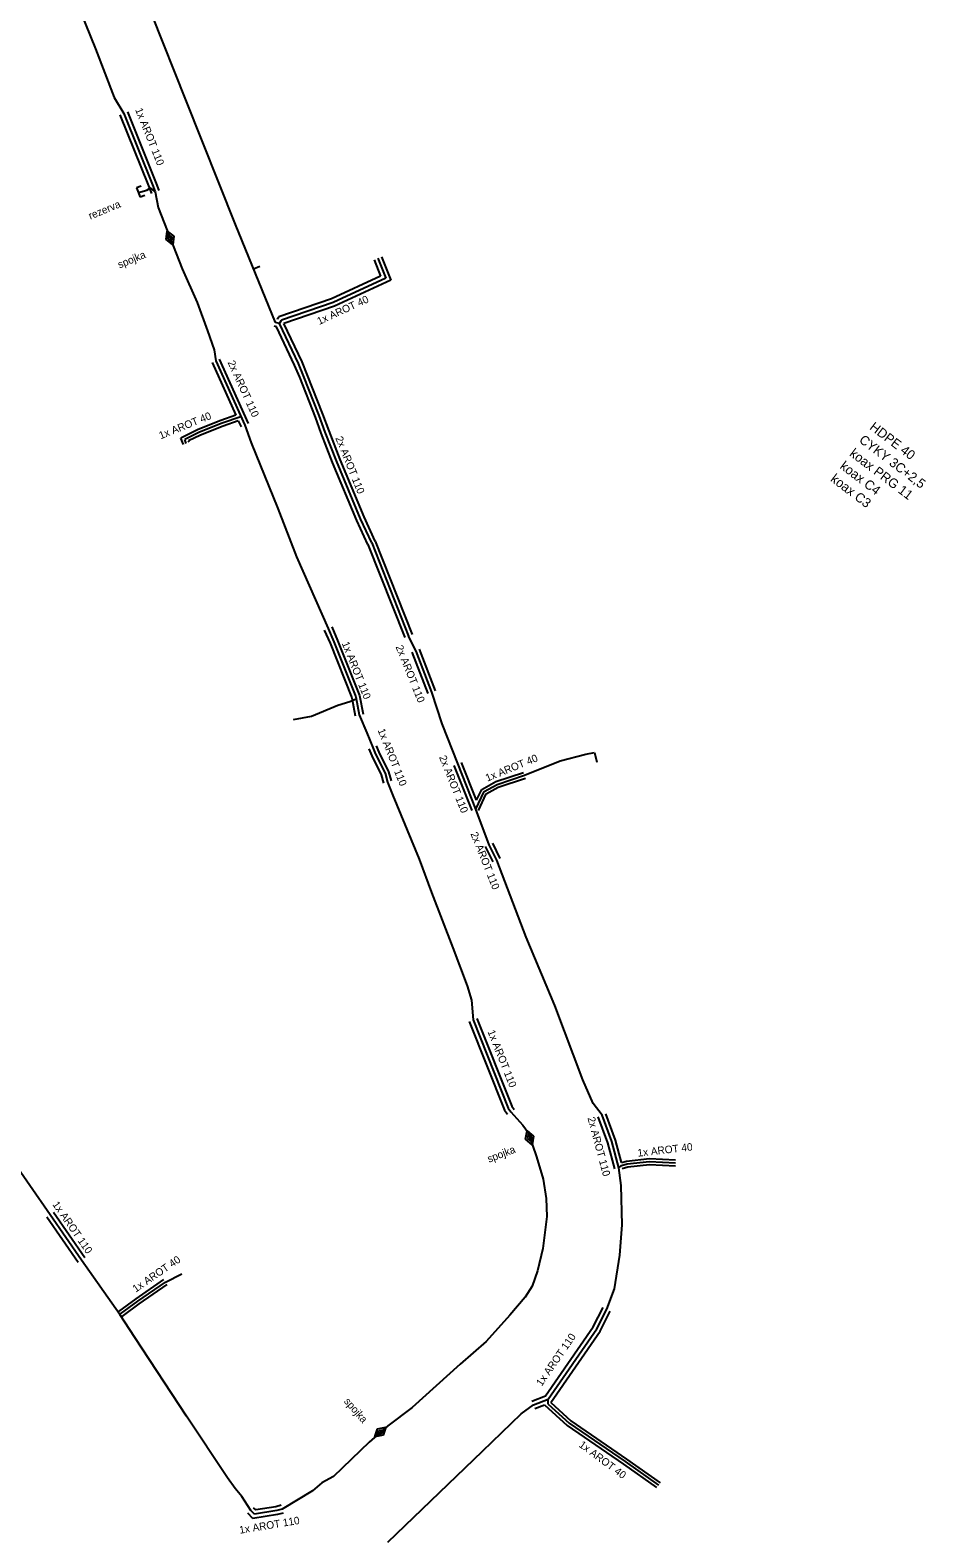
# Model space of a CAD drawing. Extents: x -651943 to -618711, y -1138561 to -1100552.
# Drawn here: x -651407.5 to -651318.3, y -1113276.7 to -1113126.5 of the extents above; entities that cross this region are included whole.
import ezdxf

# ---------------------------------------------------------------- set-up
doc = ezdxf.new("R2010")
doc.units = 0
doc.layers.add('KT trasa', color=7, linetype='Continuous')
doc.layers.add('KT zařízení', color=7, linetype='Continuous')

# ---------------------------------------------------------------- blocks, each defined once
blk = doc.blocks.new('TVSPO_1')
at = {"layer": 'KT zařízení'}
for p, q in [((-0.074, 0.002), (0, 0.044)), ((-0.001, -0.041), (-0.074, 0.002)), ((-0.035, 0), (0, 0.02)), ((0.073, 0.001), (-0.001, -0.041)), ((0, 0.044), (0.073, 0.001)), ((0, 0.02), (0.035, 0)), ((0.035, 0), (0, -0.02)), ((0, -0.02), (-0.035, 0))]:
    blk.add_line(p, q, dxfattribs=at)
blk = doc.blocks.new('TVREZ')
at = {"layer": 'KT zařízení'}
for p, q in [((-0.05, 0.05), (0, 0.05)), ((0, -0.05), (0, 0.05)), ((-0.05, -0.05), (0, -0.05))]:
    blk.add_line(p, q, dxfattribs=at)

msp = doc.modelspace()

# ---------------------------------------------------------------- linework, layer by layer
at = {"layer": 'KT trasa'}
for p, q in [((-651403.1, -1113123.29), (-651401.02, -1113128.38)), ((-651392.02, -1113133.49), (-651395.37, -1113125.03)), ((-651401.02, -1113128.38), (-651399.16, -1113133.25)), ((-651399.16, -1113133.25), (-651398.21, -1113134.82)), ((-651387.09, -1113145.9), (-651392.02, -1113133.49)), ((-651398.21, -1113134.82), (-651395.36, -1113141.93)), ((-651396.74, -1113142.71), (-651395.93, -1113142.46)), ((-651395.93, -1113142.46), (-651395.55, -1113142.24)), ((-651395.08, -1113142.64), (-651395.55, -1113142.24)), ((-651395.36, -1113141.93), (-651395.08, -1113142.64)), ((-651395.08, -1113142.64), (-651394.8, -1113144.21)), ((-651394.8, -1113144.21), (-651392.4, -1113150.29)), ((-651383.08, -1113155.63), (-651387.09, -1113145.9)), ((-651372.89, -1113149.25), (-651372.11, -1113151.23)), ((-651392.4, -1113150.29), (-651390.9, -1113153.66)), ((-651385.28, -1113150.29), (-651384.67, -1113150.04)), ((-651372.11, -1113151.23), (-651377.35, -1113153.65)), ((-651390.9, -1113153.66), (-651389.86, -1113156.46)), ((-651377.35, -1113153.65), (-651382.48, -1113155.4)), ((-651389.86, -1113156.46), (-651389.2, -1113158.36)), ((-651382.69, -1113155.75), (-651383.08, -1113155.63)), ((-651382.69, -1113155.75), (-651382.48, -1113155.4)), ((-651380.81, -1113159.72), (-651382.69, -1113155.75)), ((-651389.2, -1113158.36), (-651389.05, -1113159.47)), ((-651389.05, -1113159.47), (-651386.16, -1113165.86)), ((-651380.3, -1113160.95), (-651380.81, -1113159.72)), ((-651378.74, -1113164.92), (-651380.3, -1113160.95)), ((-651388.42, -1113165.67), (-651390.67, -1113166.58)), ((-651386.54, -1113165.03), (-651388.42, -1113165.67)), ((-651378.14, -1113166.55), (-651378.74, -1113164.92)), ((-651390.67, -1113166.58), (-651392.14, -1113167.3)), ((-651386.16, -1113165.86), (-651385.51, -1113167.62)), ((-651377.02, -1113169.43), (-651378.14, -1113166.55)), ((-651391.98, -1113167.68), (-651392.14, -1113167.3)), ((-651385.51, -1113167.62), (-651382.87, -1113174.18)), ((-651374.61, -1113175.18), (-651377.02, -1113169.43)), ((-651382.87, -1113174.18), (-651380.99, -1113178.99)), ((-651373.51, -1113177.59), (-651374.61, -1113175.18)), ((-651373.51, -1113177.59), (-651369.83, -1113186.86)), ((-651380.99, -1113178.99), (-651377.85, -1113186.11)), ((-651377.85, -1113186.11), (-651377.28, -1113187.44)), ((-651377.28, -1113187.44), (-651375.1, -1113192.9)), ((-651369.07, -1113188.37), (-651369.83, -1113186.86)), ((-651367.51, -1113192.45), (-651369.07, -1113188.37)), ((-651366.47, -1113195.61), (-651367.51, -1113192.45)), ((-651379.51, -1113194.84), (-651376.88, -1113193.75)), ((-651376.88, -1113193.75), (-651375.68, -1113193.37)), ((-651375.68, -1113193.37), (-651375.06, -1113193.13)), ((-651375.1, -1113192.9), (-651374.74, -1113194.72)), ((-651381.3, -1113195.18), (-651379.51, -1113194.84)), ((-651374.74, -1113194.72), (-651373.98, -1113196.49)), ((-651364.94, -1113199.57), (-651366.47, -1113195.61)), ((-651373.98, -1113196.49), (-651373.41, -1113197.96)), ((-651373.41, -1113197.96), (-651373.14, -1113198.61)), ((-651373.14, -1113198.61), (-651372.18, -1113200.52)), ((-651354.74, -1113199.28), (-651352.16, -1113198.61)), ((-651352.16, -1113198.61), (-651351.32, -1113198.46)), ((-651351.32, -1113198.46), (-651351.06, -1113199.42)), ((-651363.13, -1113204.1), (-651364.94, -1113199.57)), ((-651358.27, -1113200.72), (-651354.74, -1113199.28)), ((-651372.18, -1113200.52), (-651371.94, -1113201.4)), ((-651371.94, -1113201.4), (-651371.4, -1113202.73)), ((-651362.31, -1113202.35), (-651361, -1113201.64)), ((-651361, -1113201.64), (-651358.27, -1113200.72)), ((-651371.4, -1113202.73), (-651368.79, -1113209.07)), ((-651363.13, -1113204.1), (-651362.31, -1113202.35)), ((-651361.79, -1113207.66), (-651363.13, -1113204.1)), ((-651361.05, -1113209.19), (-651361.79, -1113207.66)), ((-651368.79, -1113209.07), (-651367.54, -1113212.41)), ((-651358.11, -1113216.85), (-651361.05, -1113209.19)), ((-651367.54, -1113212.41), (-651365.41, -1113217.9)), ((-651365.41, -1113217.9), (-651364.01, -1113221.69)), ((-651355.26, -1113223.64), (-651358.11, -1113216.85)), ((-651364.01, -1113221.69), (-651363.55, -1113223.12)), ((-651363.55, -1113223.12), (-651363.4, -1113225.08)), ((-651352.46, -1113231.04), (-651355.26, -1113223.64)), ((-651363.4, -1113225.08), (-651359.9, -1113233.88)), ((-651351.45, -1113233.41), (-651352.46, -1113231.04)), ((-651359.9, -1113233.88), (-651359.63, -1113234.24)), ((-651359.63, -1113234.24), (-651358.46, -1113235.57)), ((-651350.55, -1113234.58), (-651351.45, -1113233.41)), ((-651349.59, -1113237.19), (-651350.55, -1113234.58)), ((-651358.46, -1113235.57), (-651357.93, -1113236.3)), ((-651357.93, -1113236.3), (-651357.07, -1113238.72)), ((-651348.89, -1113239.8), (-651349.59, -1113237.19)), ((-651405.55, -1113244.49), (-651409.59, -1113238.64)), ((-651357.07, -1113238.72), (-651356.43, -1113240.94)), ((-651348.05, -1113239.43), (-651345.82, -1113239.17)), ((-651345.82, -1113239.17), (-651343.23, -1113239.31)), ((-651348.89, -1113239.8), (-651348.61, -1113239.59)), ((-651348.65, -1113241.57), (-651348.89, -1113239.8)), ((-651348.61, -1113239.59), (-651348.05, -1113239.43)), ((-651356.43, -1113240.94), (-651356.13, -1113242.88)), ((-651348.55, -1113245.48), (-651348.65, -1113241.57)), ((-651356.13, -1113242.88), (-651356.06, -1113244.67)), ((-651402.41, -1113249), (-651405.55, -1113244.49)), ((-651356.06, -1113244.67), (-651356.47, -1113247.86)), ((-651348.78, -1113248.52), (-651348.55, -1113245.48)), ((-651356.47, -1113247.86), (-651356.98, -1113250.08)), ((-651398.59, -1113254.42), (-651402.41, -1113249)), ((-651349.33, -1113251.85), (-651348.78, -1113248.52)), ((-651396.82, -1113253.09), (-651394.04, -1113251.18)), ((-651394.04, -1113251.18), (-651392.44, -1113250.38)), ((-651356.98, -1113250.08), (-651357.53, -1113251.61)), ((-651358.2, -1113252.69), (-651359.74, -1113254.49)), ((-651357.53, -1113251.61), (-651358.2, -1113252.69)), ((-651350.09, -1113253.9), (-651349.33, -1113251.85)), ((-651398.53, -1113254.36), (-651396.82, -1113253.09)), ((-651351.08, -1113255.85), (-651350.09, -1113253.9)), ((-651398.59, -1113254.42), (-651398.53, -1113254.36)), ((-651397.12, -1113256.71), (-651398.59, -1113254.42)), ((-651359.74, -1113254.49), (-651362.1, -1113257.12)), ((-651355.91, -1113262.85), (-651351.08, -1113255.85)), ((-651391.96, -1113264.54), (-651397.12, -1113256.71)), ((-651362.1, -1113257.12), (-651364.69, -1113259.37)), ((-651364.69, -1113259.37), (-651369.46, -1113263.66)), ((-651357.39, -1113263.42), (-651355.91, -1113262.85)), ((-651355.92, -1113263.34), (-651355.91, -1113262.85)), ((-651355.92, -1113263.34), (-651353.83, -1113265.23)), ((-651387.86, -1113270.68), (-651391.96, -1113264.54)), ((-651369.46, -1113263.66), (-651371.89, -1113265.49)), ((-651362.48, -1113268.03), (-651358.61, -1113264.32)), ((-651358.61, -1113264.32), (-651357.39, -1113263.42)), ((-651371.89, -1113265.49), (-651373.76, -1113267.12)), ((-651353.83, -1113265.23), (-651348.26, -1113269.06)), ((-651373.76, -1113267.12), (-651377.32, -1113270.54)), ((-651371.91, -1113277.07), (-651362.48, -1113268.03)), ((-651348.26, -1113269.06), (-651344.94, -1113271.41)), ((-651387.12, -1113271.74), (-651387.86, -1113270.68)), ((-651377.32, -1113270.54), (-651378.49, -1113271.17)), ((-651386.44, -1113272.54), (-651387.12, -1113271.74)), ((-651379.4, -1113271.96), (-651382.42, -1113273.79)), ((-651378.49, -1113271.17), (-651379.4, -1113271.96)), ((-651385.55, -1113273.93), (-651386.44, -1113272.54)), ((-651382.42, -1113273.79), (-651382.96, -1113273.94)), ((-651385.2, -1113274.31), (-651385.55, -1113273.93)), ((-651382.96, -1113273.94), (-651385.2, -1113274.31))]:
    msp.add_line(p, q, dxfattribs=at)
at = {"layer": 'KT zařízení'}
for p, q in [((-651398.59, -1113134.97), (-651395.75, -1113142.05)), ((-651397.85, -1113134.67), (-651394.98, -1113141.81)), ((-651395.75, -1113142.05), (-651395.46, -1113142.79)), ((-651394.98, -1113141.81), (-651394.72, -1113142.49)), ((-651372.53, -1113149.1), (-651371.6, -1113151.44)), ((-651373.27, -1113149.4), (-651372.63, -1113151.03)), ((-651372.63, -1113151.03), (-651377.51, -1113153.28)), ((-651371.6, -1113151.44), (-651377.21, -1113154.02)), ((-651377.51, -1113153.28), (-651382.76, -1113155.07)), ((-651382.88, -1113155.28), (-651382.97, -1113155.25)), ((-651382.88, -1113155.28), (-651382.76, -1113155.07)), ((-651377.21, -1113154.02), (-651382.26, -1113155.74)), ((-651382.99, -1113156.08), (-651383.21, -1113156.01)), ((-651381.19, -1113159.88), (-651382.99, -1113156.08)), ((-651380.45, -1113159.56), (-651382.26, -1113155.74)), ((-651389.42, -1113159.63), (-651387.05, -1113164.88)), ((-651388.7, -1113159.31), (-651385.81, -1113165.7)), ((-651379.94, -1113160.81), (-651380.45, -1113159.56)), ((-651380.68, -1113161.09), (-651381.19, -1113159.88)), ((-651379.12, -1113165.06), (-651380.68, -1113161.09)), ((-651378.38, -1113164.78), (-651379.94, -1113160.81)), ((-651388.54, -1113165.39), (-651390.8, -1113166.3)), ((-651387.05, -1113164.88), (-651388.54, -1113165.39)), ((-651386.8, -1113165.43), (-651388.32, -1113165.95)), ((-651386.8, -1113165.43), (-651386.53, -1113166.02)), ((-651378.54, -1113166.66), (-651379.12, -1113165.06)), ((-651377.76, -1113166.44), (-651378.38, -1113164.78)), ((-651390.8, -1113166.3), (-651392.54, -1113167.16)), ((-651392.26, -1113167.8), (-651392.54, -1113167.16)), ((-651390.56, -1113166.86), (-651391.76, -1113167.44)), ((-651388.32, -1113165.95), (-651390.56, -1113166.86)), ((-651377.4, -1113169.58), (-651378.54, -1113166.66)), ((-651376.66, -1113169.28), (-651377.76, -1113166.44)), ((-651391.71, -1113167.56), (-651391.76, -1113167.44)), ((-651374.98, -1113175.35), (-651377.4, -1113169.58)), ((-651374.26, -1113175.01), (-651376.66, -1113169.28)), ((-651373.89, -1113177.75), (-651374.98, -1113175.35)), ((-651373.15, -1113177.43), (-651374.26, -1113175.01)), ((-651373.89, -1113177.75), (-651370.21, -1113187.01)), ((-651373.15, -1113177.43), (-651369.47, -1113186.71)), ((-651378.23, -1113186.27), (-651377.66, -1113187.58)), ((-651377.49, -1113185.95), (-651376.92, -1113187.3)), ((-651377.66, -1113187.58), (-651375.49, -1113193.01)), ((-651376.92, -1113187.3), (-651374.72, -1113192.79)), ((-651367.15, -1113192.31), (-651368.74, -1113188.18)), ((-651367.89, -1113192.59), (-651369.48, -1113188.46)), ((-651374.72, -1113192.79), (-651374.36, -1113194.64)), ((-651375.49, -1113193.01), (-651375.14, -1113194.8)), ((-651373.79, -1113198.11), (-651373.51, -1113198.78)), ((-651373.51, -1113198.78), (-651372.56, -1113200.67)), ((-651373.05, -1113197.81), (-651372.79, -1113198.44)), ((-651372.79, -1113198.44), (-651371.82, -1113200.37)), ((-651363.51, -1113204.25), (-651365.3, -1113199.74)), ((-651363.06, -1113203.22), (-651364.56, -1113199.44)), ((-651372.56, -1113200.67), (-651372.34, -1113201.51)), ((-651371.82, -1113200.37), (-651371.56, -1113201.29)), ((-651362.55, -1113202.13), (-651361.13, -1113201.36)), ((-651361.13, -1113201.36), (-651358.38, -1113200.44)), ((-651360.89, -1113201.92), (-651358.18, -1113201)), ((-651363.06, -1113203.22), (-651362.55, -1113202.13)), ((-651362.87, -1113204.23), (-651362.09, -1113202.57)), ((-651362.09, -1113202.57), (-651360.89, -1113201.92)), ((-651360.7, -1113209.02), (-651361.44, -1113207.49)), ((-651361.42, -1113209.36), (-651362.16, -1113207.83)), ((-651363.78, -1113225.23), (-651360.26, -1113234.08)), ((-651363.04, -1113224.93), (-651359.56, -1113233.68)), ((-651360.26, -1113234.08), (-651359.96, -1113234.48)), ((-651359.56, -1113233.68), (-651359.32, -1113234)), ((-651349.98, -1113237.31), (-651350.94, -1113234.72)), ((-651349.22, -1113237.07), (-651350.18, -1113234.44)), ((-651349.29, -1113239.9), (-651349.98, -1113237.31)), ((-651348.62, -1113239.28), (-651349.22, -1113237.07)), ((-651348.62, -1113239.28), (-651348.12, -1113239.14)), ((-651348.12, -1113239.14), (-651345.84, -1113238.87)), ((-651345.84, -1113238.87), (-651343.22, -1113239.01)), ((-651348.54, -1113239.88), (-651348, -1113239.72)), ((-651348, -1113239.72), (-651345.82, -1113239.47)), ((-651345.82, -1113239.47), (-651343.25, -1113239.61)), ((-651402.75, -1113249.23), (-651405.89, -1113244.72)), ((-651402.09, -1113248.77), (-651405.23, -1113244.26)), ((-651396.99, -1113252.84), (-651394.22, -1113250.93)), ((-651398.72, -1113254.12), (-651396.99, -1113252.84)), ((-651396.67, -1113253.34), (-651393.88, -1113251.43)), ((-651398.36, -1113254.6), (-651396.67, -1113253.34)), ((-651351.43, -1113255.64), (-651350.46, -1113253.72)), ((-651350.75, -1113256.06), (-651349.74, -1113254.08)), ((-651356.18, -1113262.52), (-651351.43, -1113255.64)), ((-651355.66, -1113263.18), (-651350.75, -1113256.06)), ((-651357.54, -1113263.05), (-651356.18, -1113262.52)), ((-651355.66, -1113263.18), (-651353.65, -1113265)), ((-651357.26, -1113263.79), (-651356.29, -1113263.42)), ((-651356.29, -1113263.42), (-651354.03, -1113265.47)), ((-651354.03, -1113265.47), (-651348.43, -1113269.31)), ((-651353.65, -1113265), (-651348.11, -1113268.81)), ((-651348.43, -1113269.31), (-651345.13, -1113271.65)), ((-651348.11, -1113268.81), (-651344.77, -1113271.17)), ((-651385.06, -1113273.88), (-651385.27, -1113273.66)), ((-651383.06, -1113273.55), (-651385.06, -1113273.88)), ((-651382.54, -1113273.4), (-651383.06, -1113273.55)), ((-651385.36, -1113274.74), (-651385.85, -1113274.2)), ((-651382.88, -1113274.33), (-651385.36, -1113274.74)), ((-651382.32, -1113274.18), (-651382.88, -1113274.33))]:
    msp.add_line(p, q, dxfattribs=at)

# ---------------------------------------------------------------- block references
for name, p, xscale, yscale, rotation in [('TVREZ', (-651396.75, -1113142.71), 10.000012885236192, 10.00001288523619, -157.87134844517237), ('TVSPO_1', (-651393.62, -1113147.23), 9.99999468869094, 9.999994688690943, -66.60949728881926), ('TVSPO_1', (-651357.76, -1113236.81), 9.999996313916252, 9.999996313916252, 110.56800521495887), ('TVSPO_1', (-651372.63, -1113266.13), 10.000021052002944, 10.000021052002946, 41.71780197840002)]:
    msp.add_blockref(name, p, dxfattribs=dict(at, xscale=xscale, yscale=yscale, rotation=rotation))

# ---------------------------------------------------------------- texts
for s, height, rotation, p in [('1x AROT 110', 0.75, 291.7023, (-651397.09, -1113134.45)), ('rezerva', 0.75, 22.3985, (-651401.54, -1113145.41)), ('spojka', 0.75, 22.3985, (-651398.63, -1113150.27)), ('1x AROT 40', 0.75, 24.7412, (-651378.74, -1113155.9)), ('2x AROT 110', 0.75, 294.3358, (-651387.88, -1113159.62)), ('1x AROT 40', 0.75, 22.0029, (-651394.53, -1113167.28)), ('HDPE 40', 0.938, 322.8238, (-651323.97, -1113166.22)), ('2x AROT 110', 0.75, 291.9, (-651377.14, -1113167.15)), ('CYKY 3C+2,5', 0.9375, 322.8238, (-651325.02, -1113167.5)), ('koax PRG 11', 0.9375, 322.8238, (-651325.97, -1113168.85)), ('koax C4', 0.938, 322.8238, (-651326.93, -1113170.11)), ('koax C3', 0.938, 322.8238, (-651327.87, -1113171.38)), ('1x AROT 110', 0.75, 291.7652, (-651376.5, -1113187.59)), ('2x AROT 110', 0.75, 291.9645, (-651371.14, -1113187.94)), ('1x AROT 110', 0.75, 291.8924, (-651372.93, -1113196.24)), ('2x AROT 110', 0.75, 291.7459, (-651366.81, -1113198.92)), ('1x AROT 40', 0.75, 22.0913, (-651361.99, -1113201.37)), ('2x AROT 110', 0.75, 291.8014, (-651363.68, -1113206.55)), ('1x AROT 110', 0.75, 291.6896, (-651361.98, -1113226.25)), ('2x AROT 110', 0.75, 285.0134, (-651352.01, -1113234.85)), ('spojka', 0.75, 21.0375, (-651361.82, -1113239.31)), ('1x AROT 40', 0.75, 6.6371, (-651346.98, -1113238.71)), ('1x AROT 110', 0.75, 304.8468, (-651405.36, -1113243.46)), ('1x AROT 40', 0.75, 34.4927, (-651397.02, -1113252.25)), ('1x AROT 110', 0.75, 55.3915, (-651356.57, -1113261.62)), ('spojka', 0.75, 311.0773, (-651376.32, -1113263.1)), ('1x AROT 40', 0.75, 323.3061, (-651352.93, -1113267.53)), ('1x AROT 110', 0.75, 9.3793, (-651386.64, -1113276.25))]:
    msp.add_text(s, height=height, rotation=rotation, dxfattribs=at).set_placement(p)

doc.saveas('drawing.dxf')
